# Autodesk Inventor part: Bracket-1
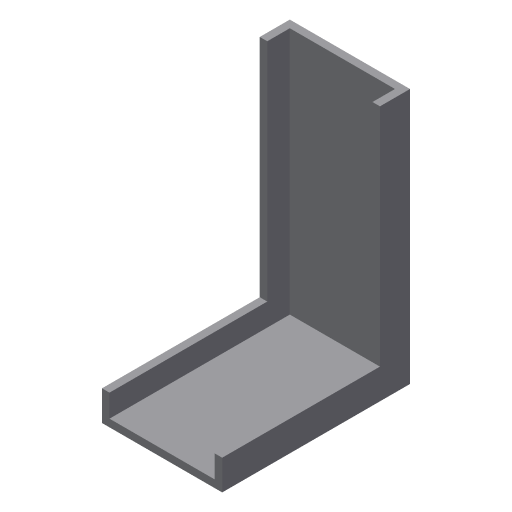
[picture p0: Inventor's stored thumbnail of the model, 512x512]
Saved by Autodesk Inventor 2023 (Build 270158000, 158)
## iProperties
Created: 2002-04
Part Number: Bracket-1
Document SubType Name: Modeling
Density: 1 g/cm^3
Material: Generic
Appearance: Default
Control State: 0
Master: False
Checked Out: False
Shininess: 77.0
Length Units: 11269
Angle Units: 11279
Time Units: 11290
Mass Units: 11283
Length Display Precision: 3
Angle Display Precision: 2
Density: 0.0
Volumn: 0.0
Area: 0.0
PropertySet Name: Model Information
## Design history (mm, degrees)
node "Sketch1"
sketch "Sketch2"
  geometry: L1 (-4.258, 23.699)-(-4.258, -18.801); L2 (-4.258, -18.801)-(26.992, -18.801); L3 (26.992, -18.801)-(26.992, -13.801); L4 (26.992, -13.801)-(0.742, -13.801); L5 (0.742, -13.801)-(0.742, 23.699); L6 (0.742, 23.699)-(-4.258, 23.699)
  constraints: 12 end point, 4 parallel, 2 perpendicular, 1 vertical
  dimensions: "d0" = 31.25 distance of L1.end L2.end; "d1" = 42.5 distance of L1.start L1.end; "d2" = 5 distance of L2.end L3.end
extrude "Extrusion1" new body sketch "Sketch2" stored distance "d3" = 20; taper "d4" = 0 deg
shell "Shell1" dims "d5" = 1.25
body "Solid1"
